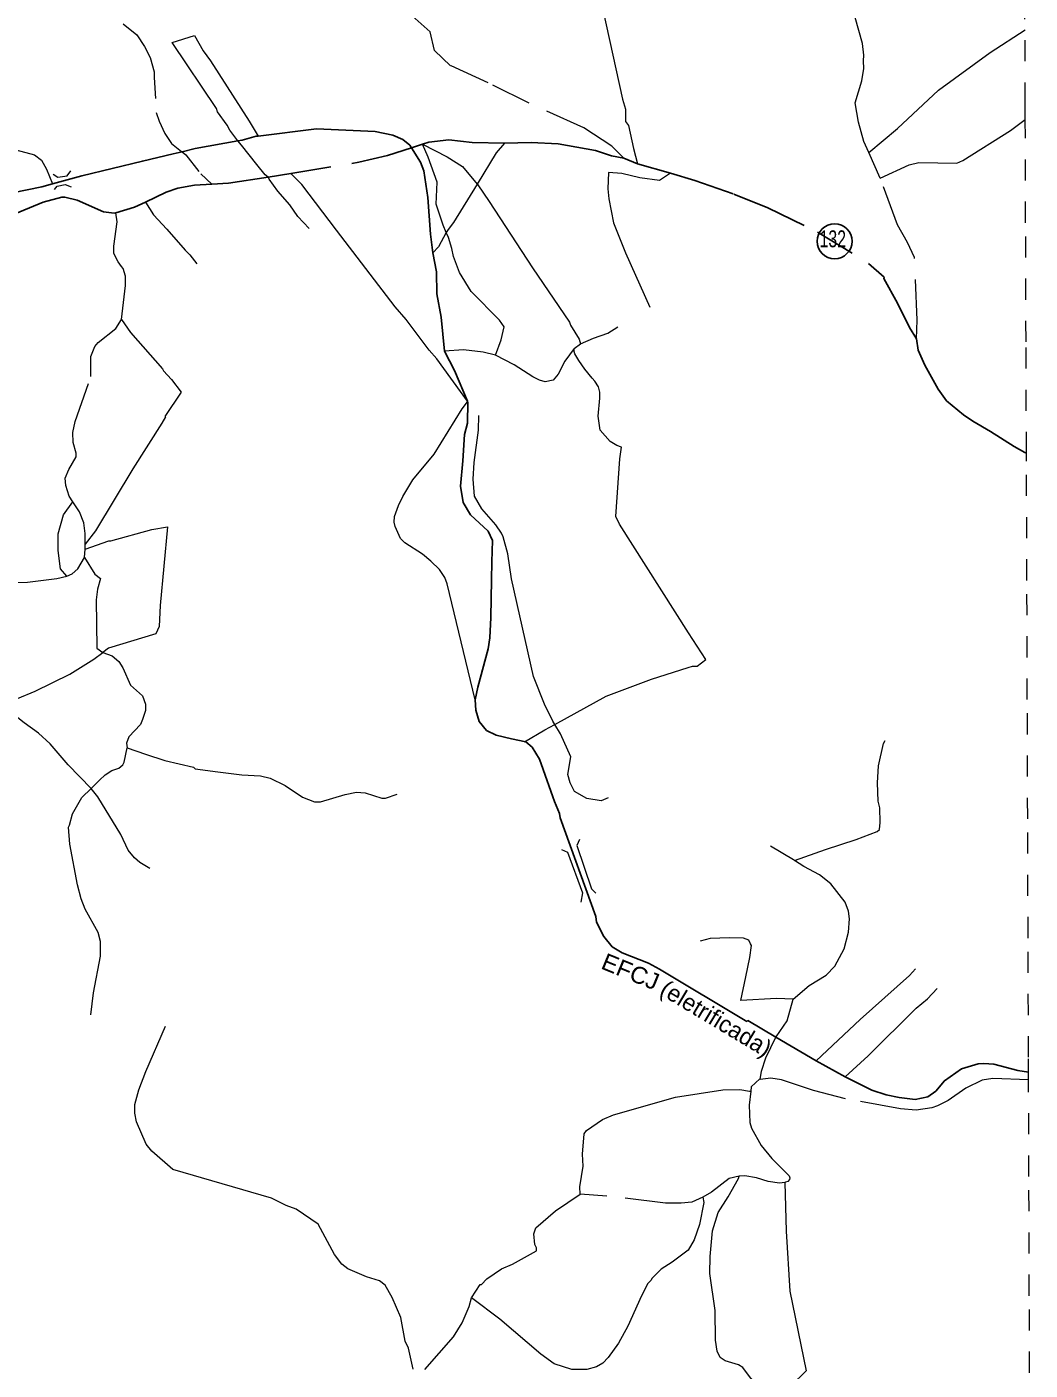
# Model space of a CAD drawing. Extents: x 423 to 448.8, y 7456.3 to 7484.
# Drawn here: x 443.98 to 448.74, y 7463.35 to 7469.71 of the extents above; entities that cross this region are included whole.
import ezdxf
from ezdxf.enums import TextEntityAlignment as Align

# ---------------------------------------------------------------- set-up
doc = ezdxf.new("R2010")
doc.units = 0
doc.header["$LTSCALE"] = 0.032
for name, pattern in [('LONG_DASHED', [7.5, 6, -1.5]), ('MEDIUM_DASHED', [4.5, 3, -1.5]), ('SHORT_DASHED', [2.7, 1.5, -1.2])]:
    doc.linetypes.add(name, pattern=pattern)
for name, color, linetype, lineweight in [('11', 7, 'Continuous', 13), ('13', 7, 'Continuous', 25), ('15', 7, 'Continuous', 25), ('35', 7, 'SHORT_DASHED', 13), ('4', 7, 'LONG_DASHED', 25), ('5', 7, 'LONG_DASHED', 13), ('6', 7, 'MEDIUM_DASHED', 13), ('7', 7, 'Continuous', 13)]:
    doc.layers.add(name, color=color, linetype=linetype, lineweight=lineweight)
doc.layers.add('61', color=7, linetype='Continuous')

msp = doc.modelspace()

# ---------------------------------------------------------------- linework, layer by layer
at = {"layer": '11'}
for points in [[(444.1059, 7469.0159), (444.1284, 7469.0018), (444.1734, 7469.0075), (444.1906, 7469.0309)], [(444.112, 7468.9433), (444.1251, 7468.9592), (444.1632, 7468.9663), (444.191, 7468.9549)], [(446.5156, 7465.8165), (446.544, 7465.8042), (446.6142, 7465.6104), (446.607, 7465.5675)], [(446.5997, 7465.8633), (446.5875, 7465.8348), (446.6565, 7465.6299), (446.6772, 7465.6098)]]:
    msp.add_lwpolyline(points, dxfattribs=at)
at = {"layer": '13'}
msp.add_circle((447.8087, 7468.698), 0.083, dxfattribs=at)
at = {"layer": '15'}
for points in [[(443.8418, 7468.9135), (444.0525, 7468.9551), (444.1039, 7468.97), (444.2426, 7469.0085), (444.5289, 7469.0776), (444.6749, 7469.1119), (444.7171, 7469.1218), (444.7799, 7469.1366), (444.982, 7469.1737), (445.0012, 7469.1772), (445.0683, 7469.1953), (445.0776, 7469.1964), (445.3543, 7469.2304), (445.6317, 7469.2176), (445.7158, 7469.2004), (445.7639, 7469.1806), (445.7962, 7469.1534), (445.8039, 7469.1411), (445.8468, 7469.072), (445.8627, 7469.0321), (445.882, 7468.9051), (445.8949, 7468.7314), (445.9059, 7468.6432), (445.9224, 7468.5531), (445.9246, 7468.4493), (445.9451, 7468.3383), (445.9612, 7468.1768), (446.0079, 7468.086), (446.0688, 7467.9403), (446.07, 7467.9375), (446.071, 7467.935), (446.07, 7467.836), (446.0561, 7467.7831), (446.0473, 7467.6572), (446.0358, 7467.5375), (446.0488, 7467.4597), (446.0839, 7467.4015), (446.167, 7467.3236), (446.1883, 7467.2809), (446.1845, 7467.1784), (446.1838, 7467.0938), (446.1801, 7466.9154), (446.1753, 7466.8197)], [(446.1753, 7466.8197), (446.1678, 7466.7676), (446.1178, 7466.5858), (446.1054, 7466.5257), (446.1089, 7466.4756), (446.1255, 7466.4229), (446.1598, 7466.38), (446.2054, 7466.3585), (446.2786, 7466.3413), (446.3456, 7466.3256), (446.3758, 7466.3014), (446.4111, 7466.244), (446.4278, 7466.1953), (446.4742, 7466.0656), (446.4819, 7466.0433), (446.5059, 7465.9865), (446.5093, 7465.9663), (446.677, 7465.4995), (446.6803, 7465.4713), (446.715, 7465.4035), (446.755, 7465.3554), (446.8031, 7465.327), (446.9265, 7465.2784), (446.9801, 7465.2497), (447.3928, 7465.0014), (447.3983, 7465.0058), (447.5311, 7464.9275), (447.7224, 7464.8147), (447.8598, 7464.7387), (447.9861, 7464.6764), (448.0536, 7464.6545), (448.1154, 7464.6406), (448.1902, 7464.6317), (448.2502, 7464.6451), (448.2881, 7464.6717), (448.3294, 7464.7203), (448.41, 7464.7765), (448.4891, 7464.8002), (448.5157, 7464.8022), (448.5638, 7464.7988), (448.6776, 7464.7692), (448.728, 7464.7616)]]:
    msp.add_lwpolyline(points, dxfattribs=at)
at = {"layer": '35'}
for points in [[(448.7127, 7469.2748), (448.7124, 7469.3503), (448.7105, 7469.9151), (448.7086, 7470.4799), (448.7067, 7471.0447), (448.7048, 7471.6095), (448.7028, 7472.1743), (448.7009, 7472.7392), (448.6995, 7473.1589)], [(448.7181, 7467.6943), (448.7162, 7468.2207), (448.7143, 7468.7855), (448.7127, 7469.2748)], [(448.7282, 7464.7245), (448.7278, 7464.8318), (448.7258, 7465.3966), (448.7239, 7465.9614), (448.722, 7466.5262), (448.7201, 7467.0911), (448.7182, 7467.6559), (448.7181, 7467.6943)], [(448.7355, 7462.5473), (448.7354, 7462.5725), (448.7335, 7463.1374), (448.7316, 7463.7022), (448.7297, 7464.267), (448.7282, 7464.7245)]]:
    msp.add_lwpolyline(points, dxfattribs=at)
at = {"layer": '4'}
for points in [[(445.2332, 7469.0183), (445.5544, 7469.0724), (445.6901, 7469.1042), (445.8039, 7469.1411), (445.856, 7469.158), (445.8859, 7469.1678), (445.9812, 7469.1781), (446.092, 7469.166), (446.2446, 7469.1631), (446.372, 7469.1652), (446.4991, 7469.1592), (446.676, 7469.1283), (446.7516, 7469.1033), (446.8097, 7469.0916), (446.8758, 7469.0645), (447.0316, 7469.02), (447.1467, 7468.9857), (447.3322, 7468.9204), (447.4919, 7468.8569), (447.7286, 7468.7417), (447.9694, 7468.5932), (448.0431, 7468.5274), (448.0424, 7468.521), (448.1077, 7468.4051), (448.1635, 7468.29), (448.1975, 7468.2363), (448.2056, 7468.1818), (448.2365, 7468.1114), (448.2992, 7467.9971), (448.3397, 7467.9425), (448.4194, 7467.8752), (448.4633, 7467.8451), (448.5483, 7467.7971), (448.6591, 7467.7257), (448.7106, 7467.6965), (448.7181, 7467.6943)], [(443.902, 7468.8182), (444.0582, 7468.8835), (444.1476, 7468.9075), (444.1622, 7468.9075), (444.2197, 7468.892), (444.3451, 7468.8371), (444.3957, 7468.8304), (444.4035, 7468.8328), (444.4911, 7468.8594), (444.5442, 7468.8829), (444.6423, 7468.9307), (444.6973, 7468.9496), (444.7763, 7468.9634), (444.8577, 7468.9686), (444.9377, 7468.9737), (445.1255, 7469.002), (445.2332, 7469.0183)]]:
    msp.add_lwpolyline(points, dxfattribs=at)
at = {"layer": '5'}
for points in [[(446.8097, 7469.0916), (446.7532, 7469.1476), (446.6211, 7469.2348), (446.3617, 7469.3524), (446.1667, 7469.4486), (445.9898, 7469.5293), (445.9127, 7469.6019), (445.8922, 7469.6902), (445.8077, 7469.7663), (445.7785, 7469.8789), (445.7553, 7469.9253), (445.7124, 7469.9879), (445.6382, 7470.0784)], [(448.1975, 7468.2363), (448.1999, 7468.3243), (448.1874, 7468.6214), (448.1544, 7468.692), (448.1071, 7468.775), (448.0251, 7468.9973), (447.9713, 7469.1179), (447.9479, 7469.1704), (447.9215, 7469.2617), (447.9061, 7469.353), (447.9379, 7469.4577), (447.9469, 7469.5156), (447.9462, 7469.5525), (447.9479, 7469.58), (447.9411, 7469.635), (447.8878, 7469.8274)], [(443.9157, 7467.0816), (443.9852, 7467.0825), (444.1235, 7467.1005), (444.1716, 7467.1117), (444.1957, 7467.122), (444.224, 7467.1452), (444.2541, 7467.1993), (444.2584, 7467.2388), (444.2584, 7467.2629), (444.2584, 7467.3127), (444.2515, 7467.3642), (444.2309, 7467.4157), (444.2001, 7467.463), (444.1828, 7467.4896), (444.1656, 7467.5411), (444.1639, 7467.5755), (444.1802, 7467.6167), (444.2146, 7467.6768), (444.2154, 7467.694), (444.2008, 7467.7438), (444.2, 7467.7919), (444.2103, 7467.8434), (444.2846, 7468.0571), (444.2841, 7468.1526), (444.303, 7468.199), (444.3194, 7468.2187), (444.4027, 7468.2849), (444.4301, 7468.3278), (444.449, 7468.4876), (444.449, 7468.5322), (444.4387, 7468.5691), (444.4301, 7468.5786), (444.4138, 7468.6001), (444.3941, 7468.6395), (444.3941, 7468.6748), (444.4095, 7468.7899), (444.4035, 7468.8328)], [(448.7282, 7464.7245), (448.5592, 7464.7317), (448.5088, 7464.7241), (448.4315, 7464.6854), (448.3473, 7464.6279), (448.2958, 7464.6013), (448.27, 7464.5927), (448.1962, 7464.5807), (448.1206, 7464.5875), (447.8612, 7464.6356), (447.7084, 7464.6743), (447.5572, 7464.7258), (447.5074, 7464.7335), (447.4559, 7464.7267), (447.4544, 7464.7296), (447.4143, 7464.6924), (447.4119, 7464.6711), (447.4043, 7464.6056), (447.4069, 7464.5232), (447.4146, 7464.4957), (447.4618, 7464.4132), (447.5116, 7464.3522), (447.5769, 7464.2878), (447.5943, 7464.2699), (447.5975, 7464.2608), (447.5958, 7464.2535), (447.5872, 7464.244), (447.5761, 7464.2397), (447.5734, 7464.2393), (447.5486, 7464.2354), (447.4936, 7464.2432), (447.4387, 7464.2612), (447.3837, 7464.2698), (447.3562, 7464.2689), (447.3098, 7464.2569), (447.2257, 7464.1933), (447.1842, 7464.1699), (447.1329, 7464.1461), (447.0814, 7464.1401), (447.0075, 7464.1409), (446.7293, 7464.1745), (446.603, 7464.1831)]]:
    msp.add_lwpolyline(points, dxfattribs=at)
at = {"layer": '6'}
msp.add_lwpolyline([(444.4386, 7469.7277), (444.5023, 7469.6752), (444.5395, 7469.6202), (444.5662, 7469.5683), (444.5847, 7469.5), (444.5852, 7469.4735), (444.595, 7469.3077), (444.6082, 7469.2667), (444.6353, 7469.2088), (444.6665, 7469.1608), (444.7151, 7469.1235), (444.7171, 7469.1218), (444.7346, 7469.1067), (444.8053, 7469.017), (444.8577, 7468.9686)], dxfattribs=at)
at = {"layer": '7'}
msp.add_line((446.575, 7468.1894), (446.6053, 7468.212), dxfattribs=at)
for points in [[(446.6494, 7470.0764), (446.804, 7469.3705), (446.8185, 7469.3241), (446.8186, 7469.2648), (446.8332, 7469.2468), (446.8555, 7469.1369), (446.8758, 7469.0645)], [(447.9713, 7469.1179), (448.1077, 7469.2325), (448.3007, 7469.4144), (448.5463, 7469.5928), (448.7112, 7469.6992)], [(445.3197, 7468.7579), (445.2663, 7468.8148), (445.2272, 7468.8699), (445.1703, 7468.9357), (445.1296, 7468.9915), (445.1267, 7469.0011), (445.1255, 7469.002), (445.1116, 7469.0125), (445.0713, 7469.0615), (444.9984, 7469.1525), (444.982, 7469.1737), (444.9433, 7469.2238), (444.9315, 7469.2473), (444.8845, 7469.3105), (444.881, 7469.3266), (444.6707, 7469.6391), (444.7754, 7469.6734), (444.8165, 7469.5999), (444.8517, 7469.5529), (445.0356, 7469.2672), (445.0776, 7469.1964)], [(443.1987, 7469.4221), (443.2413, 7469.4061), (443.2894, 7469.3945), (443.3516, 7469.3738), (443.4213, 7469.3446), (443.4974, 7469.2991), (443.7938, 7469.1583), (443.9294, 7469.1317), (444.018, 7469.107), (444.0513, 7469.0825), (444.0749, 7469.0397), (444.1039, 7468.97)], [(448.0251, 7468.9973), (448.162, 7469.0607), (448.2081, 7469.0708), (448.3882, 7469.0681), (448.417, 7469.0804), (448.6424, 7469.2218), (448.7127, 7469.2748)], [(445.9692, 7468.7391), (445.9541, 7468.7743), (445.9217, 7468.8738), (445.9266, 7468.9782), (445.8836, 7469.0964), (445.856, 7469.158), (445.9726, 7469.0979), (446.0465, 7469.0527), (446.115, 7468.969)], [(446.2446, 7469.1631), (446.2057, 7469.1162), (446.115, 7468.969)], [(446.0688, 7467.9403), (445.925, 7468.1405), (445.8872, 7468.1822), (445.7785, 7468.3269), (445.727, 7468.387), (445.4493, 7468.7503), (445.2847, 7468.9668), (445.2332, 7469.0183)], [(447.0316, 7469.02), (446.9788, 7468.9863), (446.8859, 7468.9987), (446.8005, 7469.0187), (446.7369, 7469.023), (446.7344, 7468.947), (446.7395, 7468.8981), (446.7619, 7468.7855), (446.8186, 7468.643), (446.9328, 7468.3862)], [(446.115, 7468.969), (446.0028, 7468.787), (445.9775, 7468.7541), (445.9692, 7468.7391)], [(446.115, 7468.969), (446.1182, 7468.9651), (446.1729, 7468.8862), (446.378, 7468.5726), (446.5524, 7468.3149), (446.5573, 7468.2998), (446.5994, 7468.2336), (446.6053, 7468.212)], [(444.5442, 7468.8829), (444.5816, 7468.8231), (444.6444, 7468.7553), (444.7321, 7468.6553), (444.7533, 7468.634), (444.7863, 7468.5916)], [(445.9692, 7468.7391), (445.9314, 7468.6707), (445.9059, 7468.6432)], [(446.2028, 7468.158), (446.2286, 7468.2316), (446.2431, 7468.2926), (446.2217, 7468.3235), (446.0868, 7468.4601), (446.0319, 7468.5502), (446.0027, 7468.625), (445.9961, 7468.6631), (445.9795, 7468.715), (445.9692, 7468.7391)], [(444.4301, 7468.3278), (444.4727, 7468.2653), (444.6242, 7468.0942), (444.6285, 7468.0839), (444.6672, 7468.0435), (444.7124, 7467.9827), (444.6355, 7467.8684), (444.638, 7467.8657), (444.6217, 7467.8357), (444.4842, 7467.6201), (444.3073, 7467.3255), (444.2584, 7467.2629)], [(446.6053, 7468.212), (446.666, 7468.2394), (446.7344, 7468.263), (446.7823, 7468.2919)], [(446.2028, 7468.158), (446.1441, 7468.1727), (446.0508, 7468.1827), (445.9612, 7468.1768)], [(446.575, 7468.1894), (446.531, 7468.1291), (446.4991, 7468.0685), (446.4759, 7468.0393), (446.4372, 7468.0323), (446.4106, 7468.0393), (446.3789, 7468.0556), (446.2908, 7468.1122), (446.2028, 7468.158)], [(446.4834, 7466.4088), (446.7264, 7466.542), (446.9419, 7466.624), (447.1148, 7466.6786), (447.1354, 7466.6844), (447.1584, 7466.6841), (447.1983, 7466.7171), (447.1168, 7466.8431), (446.7899, 7467.3574), (446.7723, 7467.3932), (446.7912, 7467.6664), (446.8, 7467.723), (446.7775, 7467.7298), (446.7462, 7467.7484), (446.6983, 7467.8032), (446.6881, 7467.8687), (446.6963, 7467.9538), (446.6963, 7467.9832), (446.6904, 7468.0077), (446.6729, 7468.0346), (446.6595, 7468.0492), (446.6249, 7468.0925), (446.5965, 7468.1336), (446.5776, 7468.1647), (446.5753, 7468.1758), (446.575, 7468.1894)], [(446.1054, 7466.5257), (445.9726, 7467.0747), (445.9614, 7467.1048), (445.9365, 7467.1434), (445.8962, 7467.183), (445.8567, 7467.2147), (445.7725, 7467.2697), (445.7519, 7467.2894), (445.7261, 7467.3461), (445.7227, 7467.3676), (445.7235, 7467.3934), (445.7424, 7467.4467), (445.7639, 7467.4887), (445.8111, 7467.5669), (445.9115, 7467.6895), (446.0446, 7467.9047), (446.07, 7467.9375)], [(446.4834, 7466.4088), (446.4743, 7466.4235), (446.4349, 7466.5045), (446.3823, 7466.6362), (446.2775, 7467.098), (446.2612, 7467.2165), (446.238, 7467.2972), (446.2311, 7467.3152), (446.2045, 7467.3547), (446.1367, 7467.4303), (446.1031, 7467.4904), (446.0972, 7467.5711), (446.1006, 7467.6502), (446.1212, 7467.803), (446.1238, 7467.8726)], [(444.1716, 7467.1117), (444.1412, 7467.1454), (444.1304, 7467.2328), (444.1304, 7467.3118), (444.1553, 7467.4011), (444.2001, 7467.463)], [(444.2584, 7467.2388), (444.37, 7467.2792), (444.3803, 7467.2783), (444.5744, 7467.3315), (444.6474, 7467.3453), (444.6131, 7466.9717), (444.6079, 7466.8729), (444.5925, 7466.8385), (444.3679, 7466.77), (444.3417, 7466.7501)], [(444.2541, 7467.1993), (444.3034, 7467.1211), (444.3304, 7467.1005), (444.3163, 7467.049), (444.3098, 7466.9988), (444.3129, 7466.7696), (444.3417, 7466.7501)], [(443.9001, 7466.4709), (443.9003, 7466.4741), (443.9111, 7466.504), (443.9375, 7466.5314), (444.0206, 7466.5658), (444.1849, 7466.6467), (444.2994, 7466.7178), (444.3417, 7466.7501)], [(444.3417, 7466.7501), (444.3424, 7466.7496), (444.3864, 7466.7339), (444.4177, 7466.7065), (444.4362, 7466.6762), (444.4731, 7466.5955), (444.5297, 7466.5449), (444.5443, 7466.5053), (444.5444, 7466.4753), (444.5298, 7466.4315), (444.5194, 7466.4092), (444.4645, 7466.3499), (444.4533, 7466.3199), (444.4572, 7466.298)], [(444.2861, 7466.1055), (444.1768, 7466.2176), (444.0917, 7466.3172), (444.0368, 7466.3679), (443.9687, 7466.4163), (443.9001, 7466.4709)], [(446.3397, 7466.327), (446.4363, 7466.383), (446.4834, 7466.4088)], [(446.7363, 7466.0608), (446.7023, 7466.0474), (446.6347, 7466.0579), (446.5772, 7466.0918), (446.5558, 7466.1316), (446.5453, 7466.171), (446.5597, 7466.2555), (446.5106, 7466.3649), (446.4834, 7466.4088)], [(447.6184, 7465.7646), (447.7666, 7465.8158), (447.9118, 7465.8644), (448.0107, 7465.9008), (448.0214, 7465.911), (448.0253, 7465.9443), (448.0233, 7466.0144), (448.0155, 7466.0448), (448.0116, 7466.1325), (448.017, 7466.2119), (448.0409, 7466.3187), (448.0487, 7466.3319)], [(444.2861, 7466.1055), (444.3257, 7466.1441), (444.3535, 7466.1706), (444.3849, 7466.1902), (444.4171, 7466.202), (444.4357, 7466.2176), (444.4435, 7466.2304), (444.4572, 7466.298)], [(444.4572, 7466.298), (444.5444, 7466.2674), (444.6362, 7466.2382), (444.7719, 7466.2056), (444.7788, 7466.1987), (444.8862, 7466.1841), (444.9996, 7466.1695), (445.088, 7466.1653), (445.1353, 7466.1549), (445.2057, 7466.1188), (445.2872, 7466.0647), (445.3448, 7466.0424), (445.3731, 7466.0416), (445.4899, 7466.0768), (445.5441, 7466.0879), (445.5853, 7466.0845), (445.6643, 7466.0587), (445.6806, 7466.0588), (445.7356, 7466.0785)], [(444.285, 7465.0324), (444.2978, 7465.137), (444.3314, 7465.3116), (444.3314, 7465.3803), (444.3194, 7465.4223), (444.2584, 7465.5332), (444.2386, 7465.583), (444.2214, 7465.6482), (444.1853, 7465.8423), (444.1785, 7465.9222), (444.1845, 7465.9308), (444.1974, 7465.9849), (444.2414, 7466.062), (444.2861, 7466.1055)], [(444.5649, 7465.7262), (444.5176, 7465.7547), (444.4925, 7465.776), (444.461, 7465.8131), (444.4277, 7465.8873), (444.3185, 7466.0665), (444.2864, 7466.1052), (444.2861, 7466.1055)], [(447.6184, 7465.7646), (447.6146, 7465.7671), (447.5048, 7465.8328)], [(447.6126, 7465.1079), (447.6888, 7465.1712), (447.7693, 7465.2215), (447.8105, 7465.2643), (447.8543, 7465.3459), (447.8749, 7465.4249), (447.8801, 7465.4885), (447.875, 7465.5237), (447.8586, 7465.5675), (447.7908, 7465.6534), (447.7375, 7465.6955), (447.6637, 7465.735), (447.6184, 7465.7646)], [(447.6126, 7465.1079), (447.534, 7465.1105), (447.3643, 7465.101), (447.3877, 7465.2127), (447.407, 7465.304), (447.4151, 7465.3611), (447.4111, 7465.3697), (447.4033, 7465.3866), (447.3773, 7465.3968), (447.311, 7465.3981), (447.2194, 7465.3939), (447.172, 7465.3822)], [(448.1922, 7465.2516), (448.1638, 7465.2197), (447.9308, 7465.0101), (447.7224, 7464.8147)], [(447.8598, 7464.7387), (447.9678, 7464.8385), (448.1953, 7465.0642), (448.2494, 7465.1089), (448.2949, 7465.1578)], [(447.4559, 7464.7267), (447.4632, 7464.7659), (447.4837, 7464.8291), (447.5311, 7464.9275), (447.5316, 7464.9286), (447.5847, 7465.0046), (447.6126, 7465.1079)], [(445.8123, 7463.3536), (445.7902, 7463.4531), (445.7736, 7463.4863), (445.7543, 7463.5992), (445.7128, 7463.6934), (445.6796, 7463.7515), (445.652, 7463.7723), (445.5912, 7463.7918), (445.503, 7463.8299), (445.4742, 7463.8525), (445.439, 7463.8977), (445.3624, 7464.0406), (445.2582, 7464.113), (445.2105, 7464.1293), (445.1402, 7464.1645), (444.6732, 7464.2998), (444.5742, 7464.3878), (444.5477, 7464.4201), (444.5005, 7464.5257), (444.4928, 7464.5678), (444.4928, 7464.6081), (444.5117, 7464.6777), (444.5452, 7464.7644), (444.6389, 7464.9792)], [(446.0887, 7463.693), (446.1302, 7463.7554), (446.1358, 7463.7553), (446.1615, 7463.7819), (446.2302, 7463.8292), (446.2827, 7463.8515), (446.396, 7463.9142), (446.3969, 7463.9297), (446.3891, 7463.9443), (446.3832, 7463.996), (446.393, 7464.0234), (446.486, 7464.1042), (446.603, 7464.1831), (446.6014, 7464.2175), (446.6171, 7464.316), (446.6151, 7464.3733), (446.622, 7464.4699), (446.6327, 7464.4846), (446.71, 7464.537), (446.7619, 7464.5592), (447.0556, 7464.6434), (447.2789, 7464.6777), (447.3596, 7464.6786), (447.4055, 7464.6711), (447.4119, 7464.6711)], [(447.6742, 7463.346), (447.6004, 7463.2744), (447.5671, 7463.2568), (447.4986, 7463.2565), (447.455, 7463.2752), (447.4155, 7463.307), (447.3734, 7463.3628), (447.3536, 7463.3749), (447.2901, 7463.3938), (447.266, 7463.4092), (447.2531, 7463.4393), (447.2446, 7463.4916), (447.2437, 7463.6317), (447.2179, 7463.8077), (447.2188, 7463.8884), (447.2303, 7464.0096), (447.2566, 7464.0963), (447.3042, 7464.1709), (447.3541, 7464.2577), (447.3562, 7464.2689)], [(447.5734, 7464.2393), (447.5793, 7464.0084), (447.5962, 7463.7231), (447.6742, 7463.346)], [(447.1842, 7464.1699), (447.1891, 7464.1431), (447.1695, 7464.0392), (447.1441, 7463.9671), (447.1157, 7463.9181), (447.0394, 7463.8608), (446.9866, 7463.8284), (446.9422, 7463.7837), (446.9405, 7463.7759), (446.9242, 7463.7596), (446.8933, 7463.7021), (446.8289, 7463.5578), (446.7851, 7463.4771), (446.7361, 7463.4101), (446.7112, 7463.3834), (446.6812, 7463.3646), (446.6348, 7463.3534), (446.5644, 7463.3525), (446.481, 7463.3791), (446.4175, 7463.4247), (446.2234, 7463.5913), (446.0887, 7463.693)], [(445.8676, 7463.3523), (446.003, 7463.5074), (446.0445, 7463.5739), (446.0776, 7463.6514), (446.0887, 7463.693)]]:
    msp.add_lwpolyline(points, dxfattribs=at)

# ---------------------------------------------------------------- texts
at = {"layer": '61', "width": 0.7}
msp.add_text('132', height=0.08, dxfattribs=at).set_placement((447.8005, 7468.6694), align=Align.CENTER)
at = {"layer": '61', "width": 1.05}
msp.add_text('EFCJ', height=0.08, rotation=337.747, dxfattribs=at).set_placement((446.8268, 7465.2007), align=Align.CENTER)
at = {"layer": '61'}
msp.add_text('(eletrificada)', height=0.08, rotation=329.004, dxfattribs=at).set_placement((447.2269, 7464.9818), align=Align.CENTER)

doc.saveas('drawing.dxf')
